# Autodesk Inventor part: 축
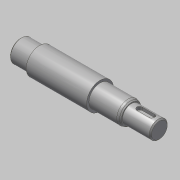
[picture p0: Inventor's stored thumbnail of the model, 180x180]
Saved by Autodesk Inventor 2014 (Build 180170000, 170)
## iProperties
Created: 2016-06
Part Number: 축
Material: 강철, 연강
Document SubType Name: Modeling
Designer: mduedu
Density: 7.86 g/cm^3
Appearance: 강철
Author: mduedu
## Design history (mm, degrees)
sketch "스케치1"
  geometry: L1 (-62, 0)-(62, 0); L2 (-62, 0)-(-62, 10); L3 (-62, 10)-(-45, 10); L4 (-45, 10)-(-45, 12); L5 (-45, 12)-(9, 12); L6 (9, 12)-(9, 10); L7 (9, 10)-(37, 10); L8 (37, 10)-(37, 8); L9 (37, 8)-(62, 8); L10 (62, 8)-(62, 0); 2 further points
  constraints: 20 end point, 5 parallel, 2 perpendicular, 1 coincident, 1 collinear, 1 horizontal, 1 midpoint, 1 vertical
  dimensions: "d0" = 124 distance of L1.start L1.end; "d2" = 16 diameter of L9 L1; "d3" = 20 diameter of L7 L1; "d4" = 24 diameter of L5 L1; "d5" = 20 diameter of L3 L1; "d6" = 17 distance of L2.end L3.end; "d7" = 25 distance of L8.end L9.end; "d8" = 53 distance from line of L5.end L10
revolve "회전1" sketch "스케치1" stored, may be unused: angle "d9" = 90 deg
chamfer "모따기1" distance "d10" = 2; stored, may be unused: second distance "d11" = 2, angle "d12" = 30 deg
fillet "모깎기1" dims "d13" = 4
node "작업 평면1"
sketch "스케치2"
  geometry: L1 (-5, 2.5)-(6, 2.5); L2 (6, -2.5)-(-5, -2.5); L3 (-5, 0)-(6, 0); L4 (-12.5, 8.845)-(-12.5, -8.845) reference; A1 r 2.5 centre (-5, 0) between (-5, 2.5) and (-5, -2.5); A2 r 2.5 centre (6, 0) between (6, -2.5) and (6, 2.5); 1 further point
  constraints: 6 end point, 4 point on circle, 3 tangent, 2 centre point, 2 parallel, 1 horizontal, 1 horizontal alignment
  dimensions: "d14" = 5 distance edge to line of A1 L4; "d15" = 5 distance between parallel lines of L2 L1; "d16" = 16 dimension on A2 A1
extrude "돌출1" cut sketch "스케치2" distance "d17" = 3; taper "d18" = 0 deg
chamfer "모따기2" distance "d19" = 1; stored, may be unused: second distance "d20" = 2, angle "d21" = 30 deg
sketch "스케치3"
  geometry: L1 (-37, -8)-(-61, -8) reference; L2 (-62, -7)-(-62, 7) reference; L3 (-38.5, -8)-(-40, -6.5); L4 (-40, -6.5)-(-40, -8); L5 (-38.5, -8)-(-40, -8); 1 further point
  constraints: 6 end point, 2 point on line, 1 collinear, 1 vertical
  dimensions: "d22" = 45 deg angle of L4 L3; "d23" = 22 distance between parallel lines of L2 L4; "d24" = 3 diameter of L3.start L4
revolve "회전2" stored, may be unused: angle "d25" = 90 deg
node "작업점1"
sketch "스케치4"
  geometry: 1 further point
hole "구멍1" sketch "스케치4" at (0, 0) diameter "d26" = 3.242; stored, may be unused: countersink angle "d30" = 90 deg, drill point angle "d32" = 120 deg; dims "d27" = 8, "d28" = 4, "d29" = 2, "d31" = 11
chamfer "모따기3" distance "d33" = 2; stored, may be unused: second distance "d34" = 2, angle "d35" = 30 deg
node "솔리드1"
